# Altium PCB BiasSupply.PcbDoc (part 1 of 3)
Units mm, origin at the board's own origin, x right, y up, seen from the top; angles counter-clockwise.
Board outline 39 x 40.5 mm, 4 copper layers (Top Layer, Layer 2, Layer3, Bottom Layer), stack 0.661 mm thick; 168 components, 80 nets, 408 pads, 115 vias.
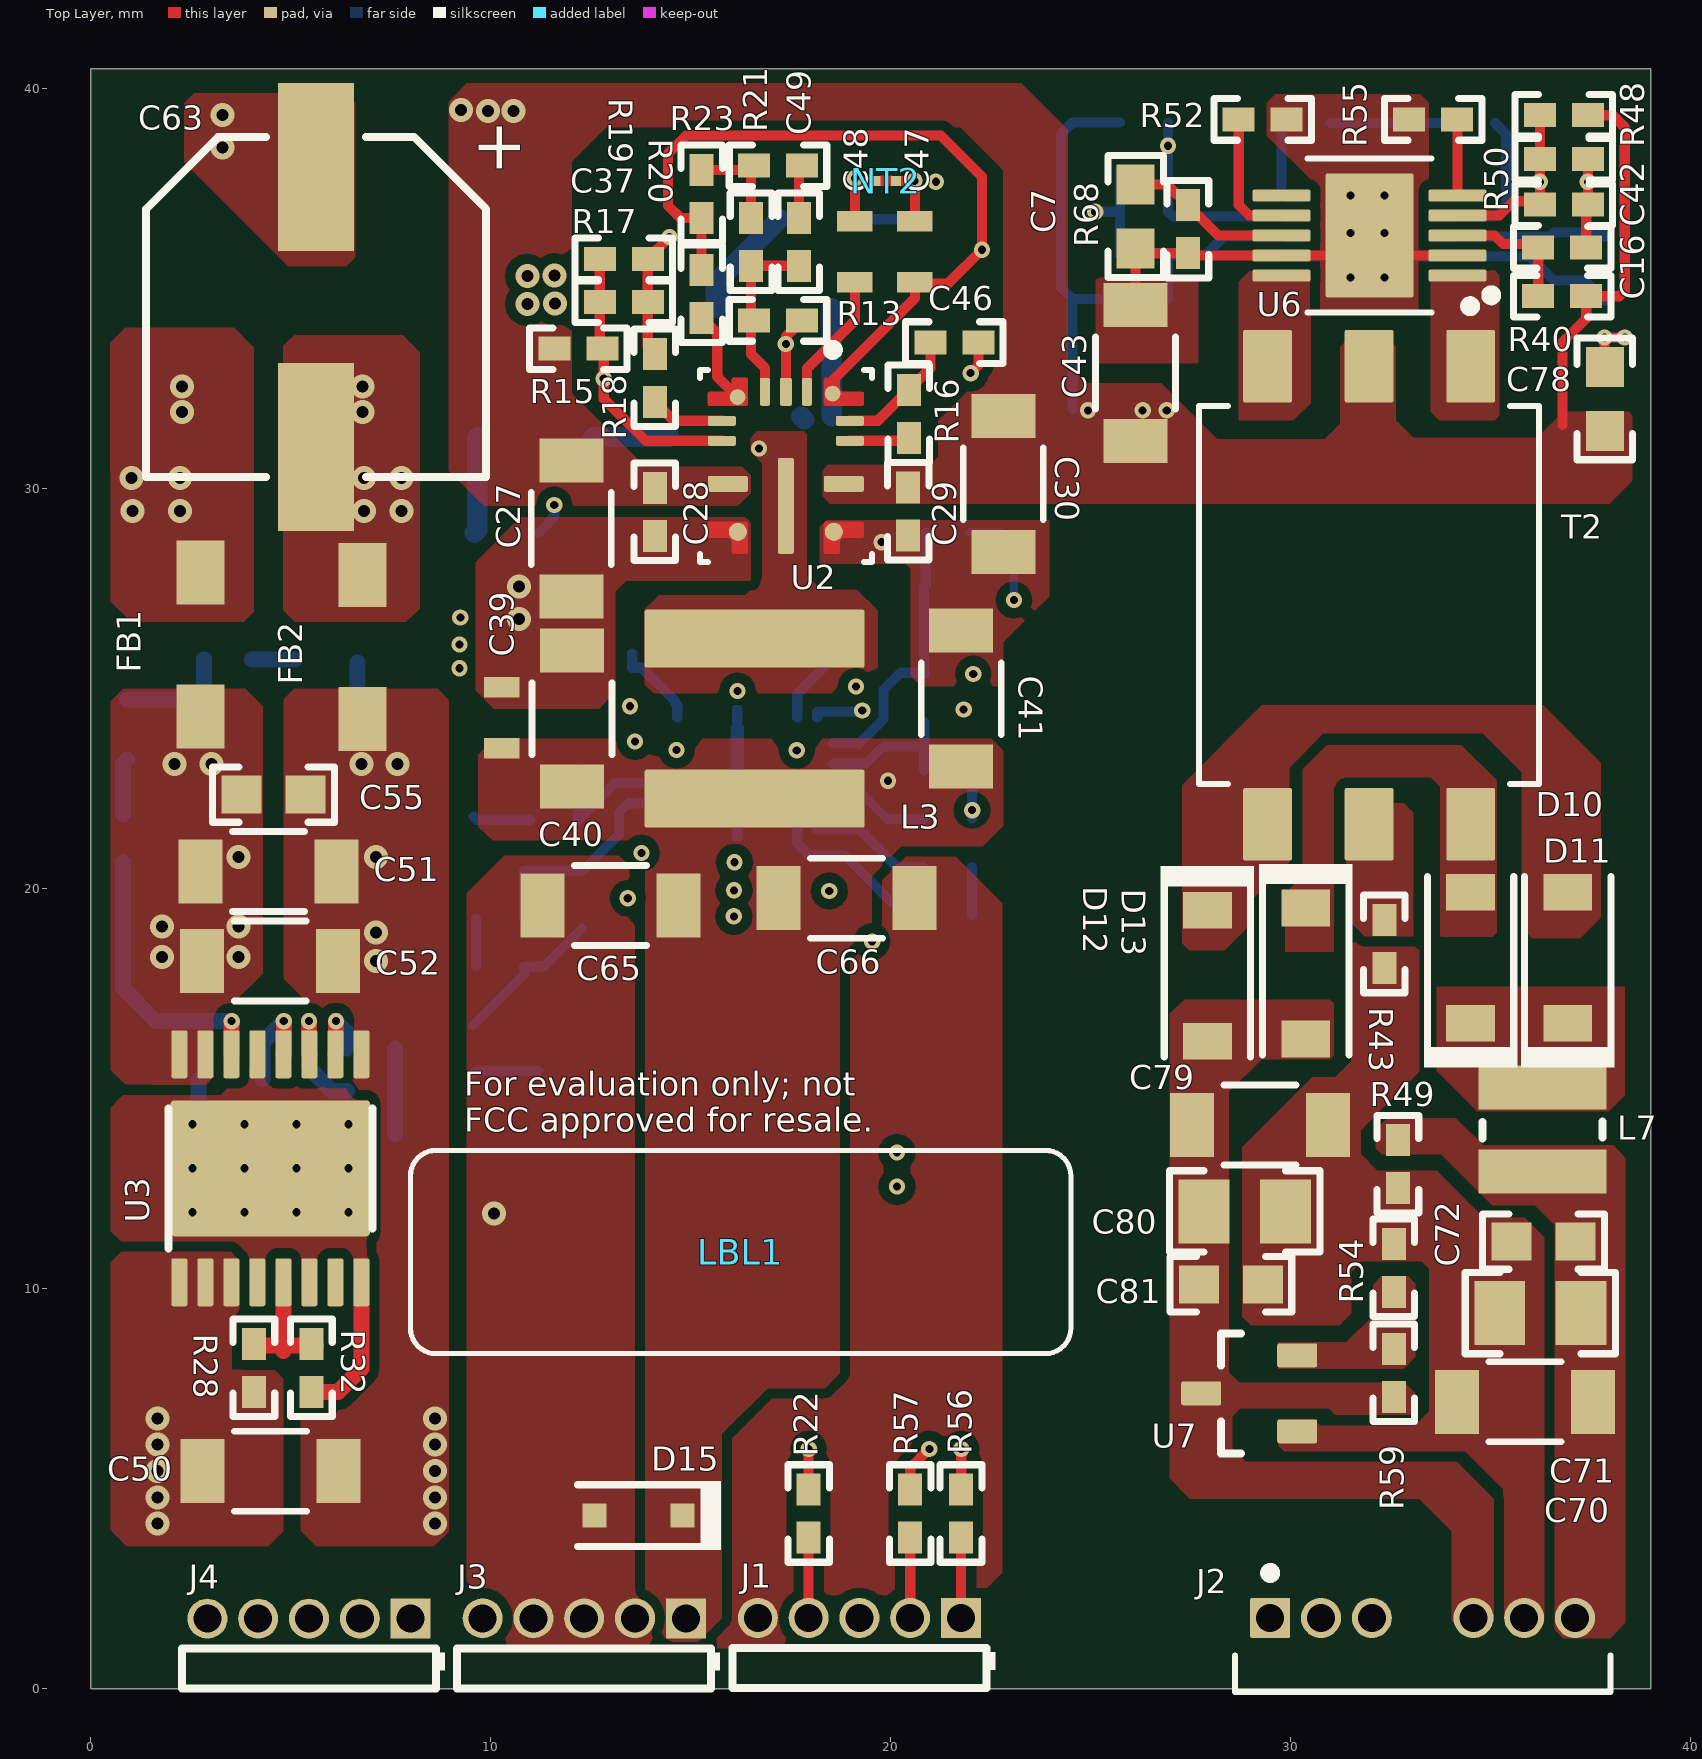
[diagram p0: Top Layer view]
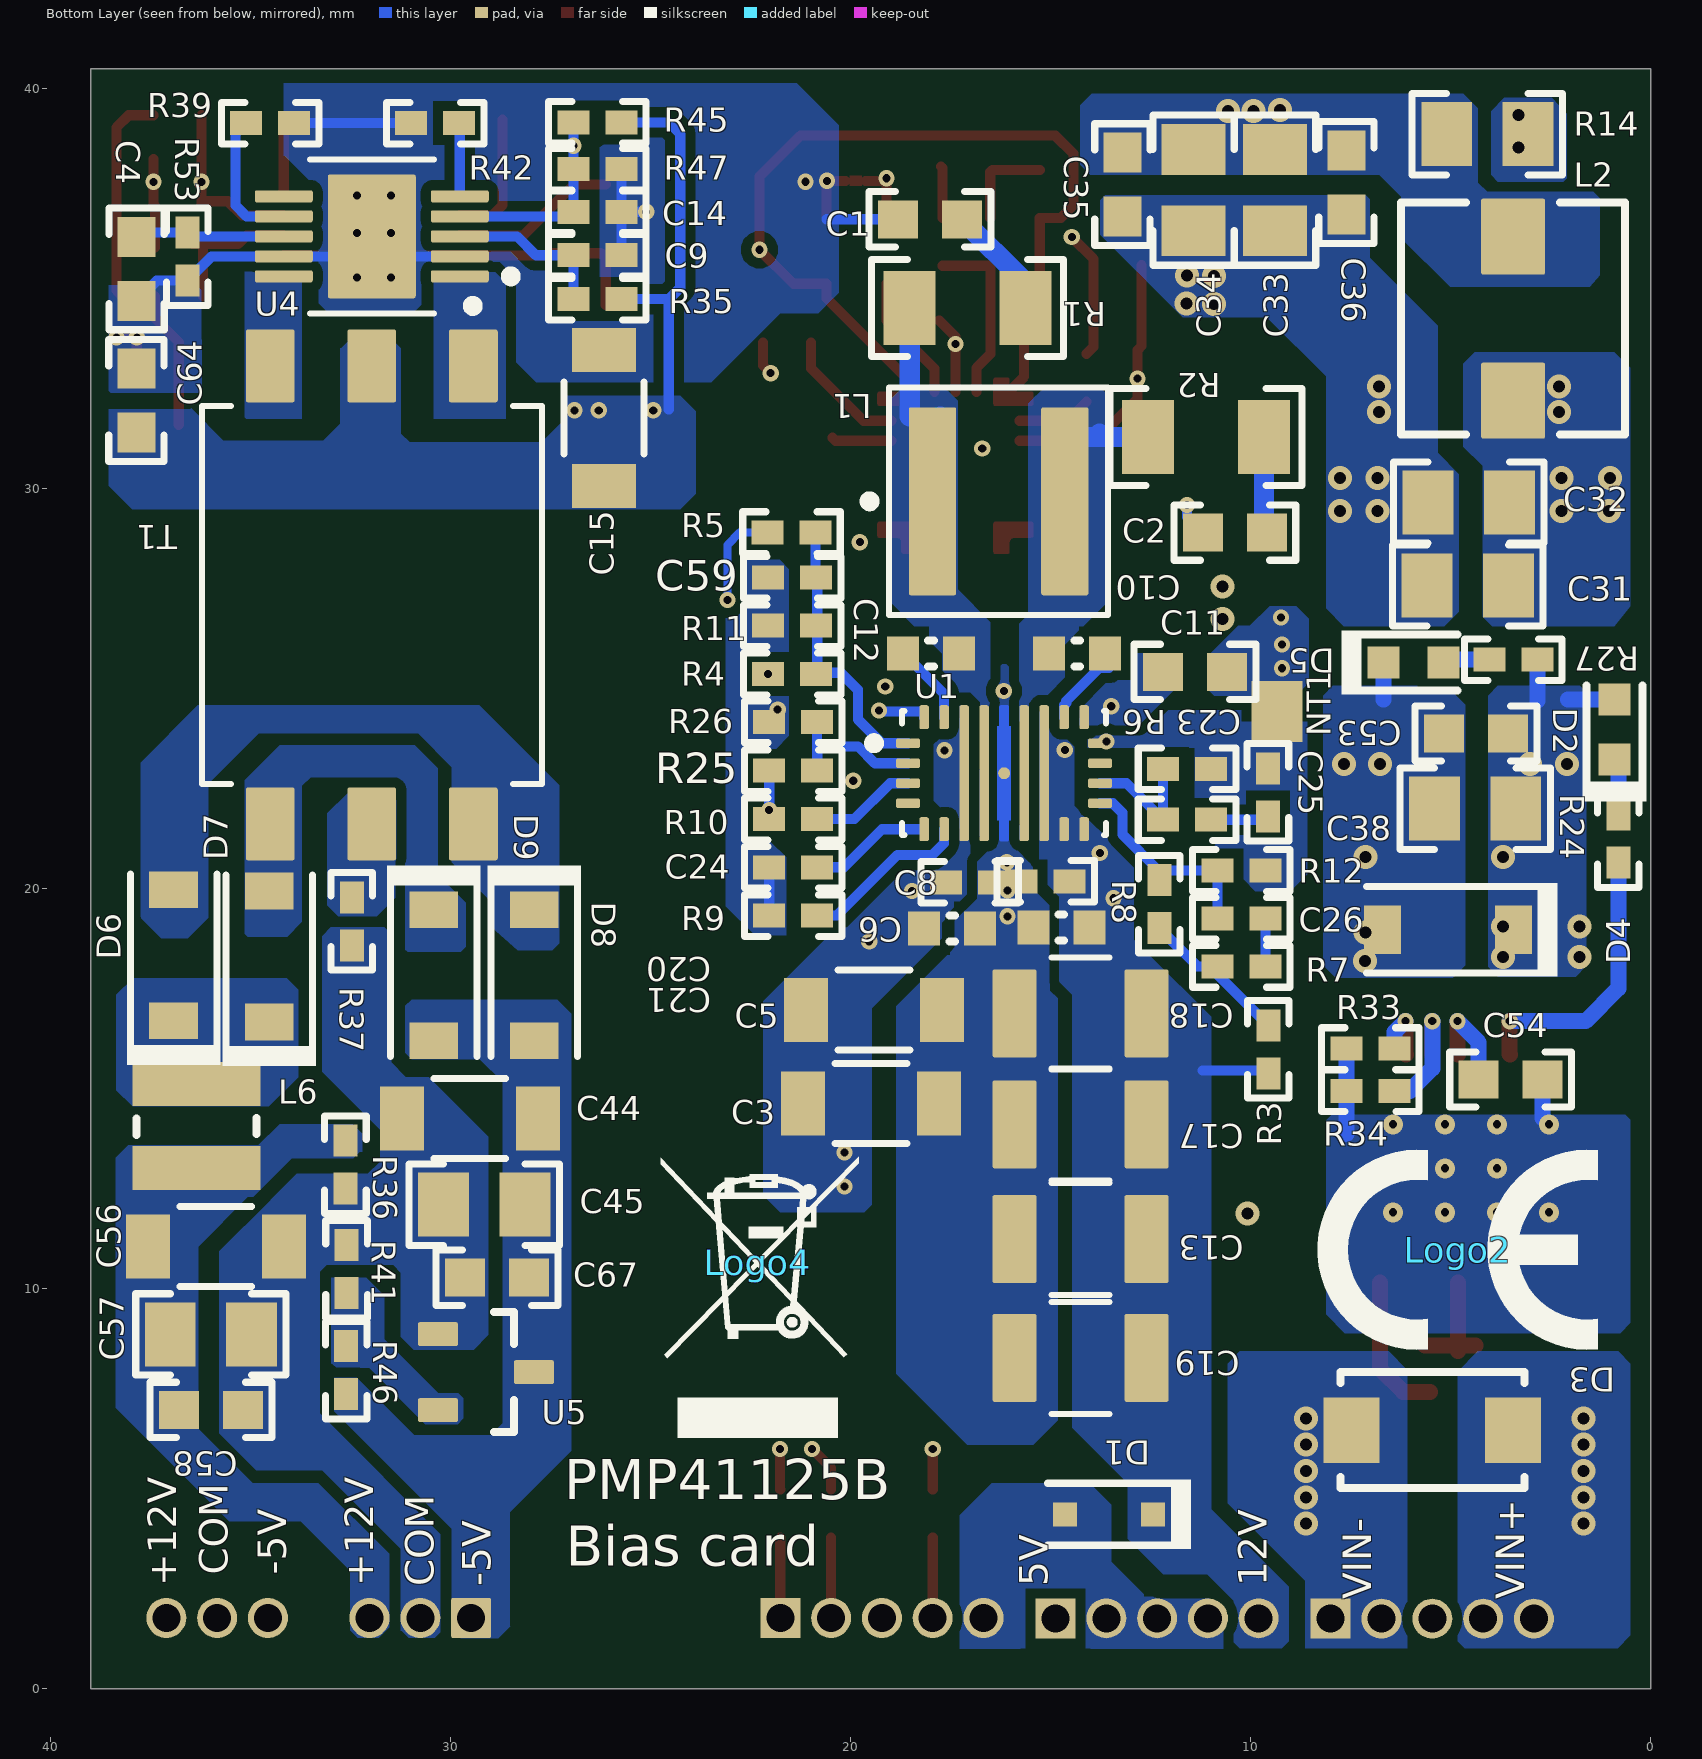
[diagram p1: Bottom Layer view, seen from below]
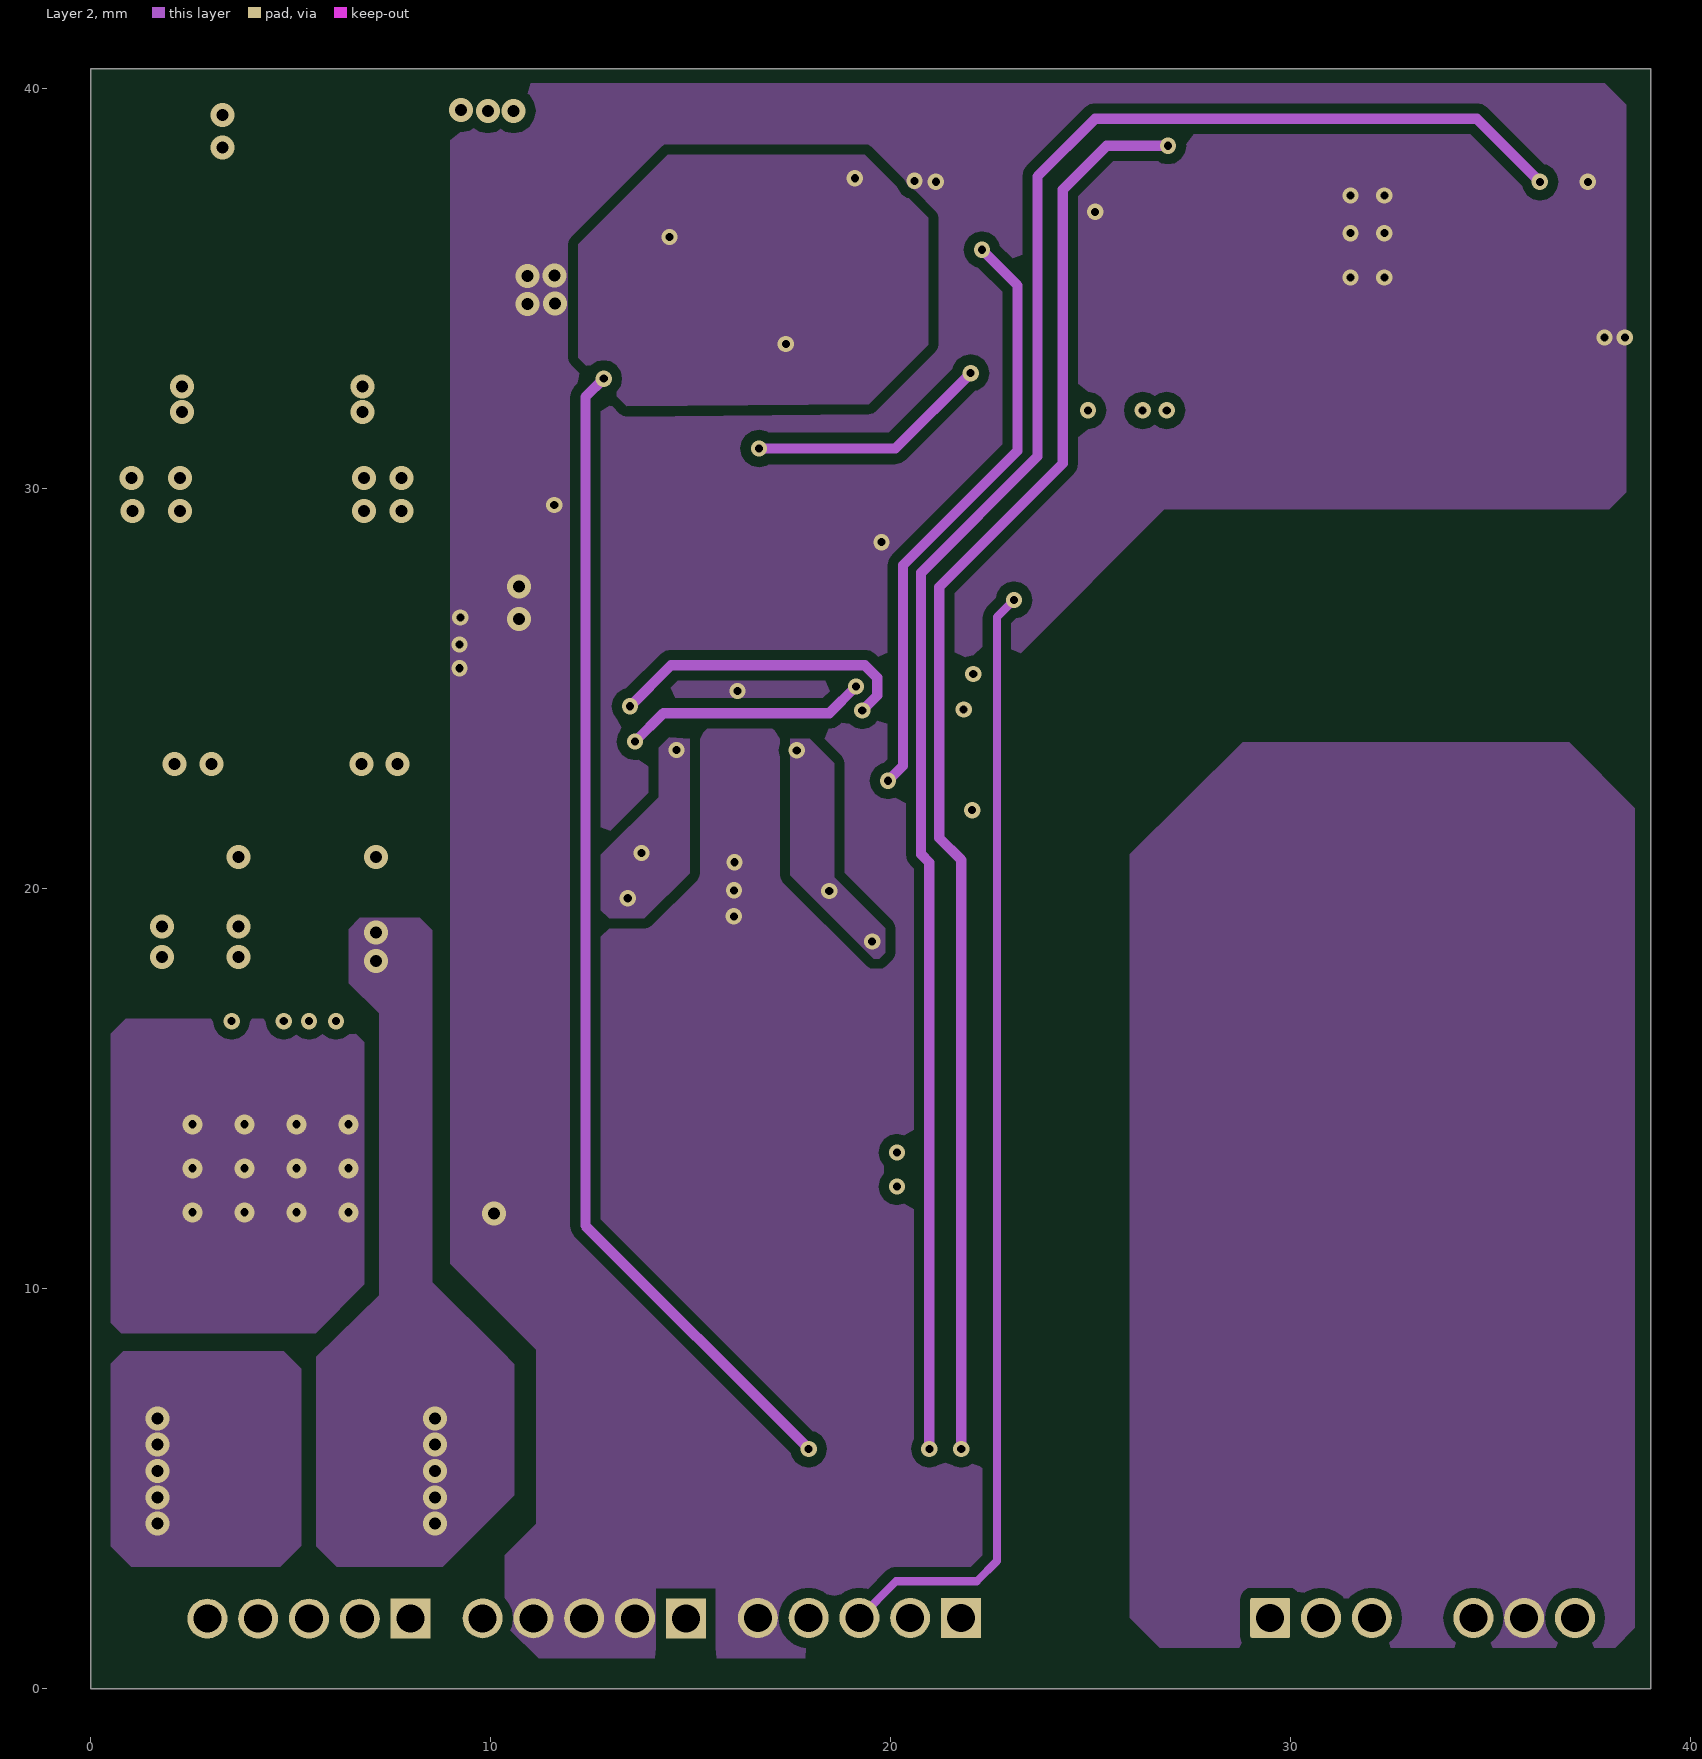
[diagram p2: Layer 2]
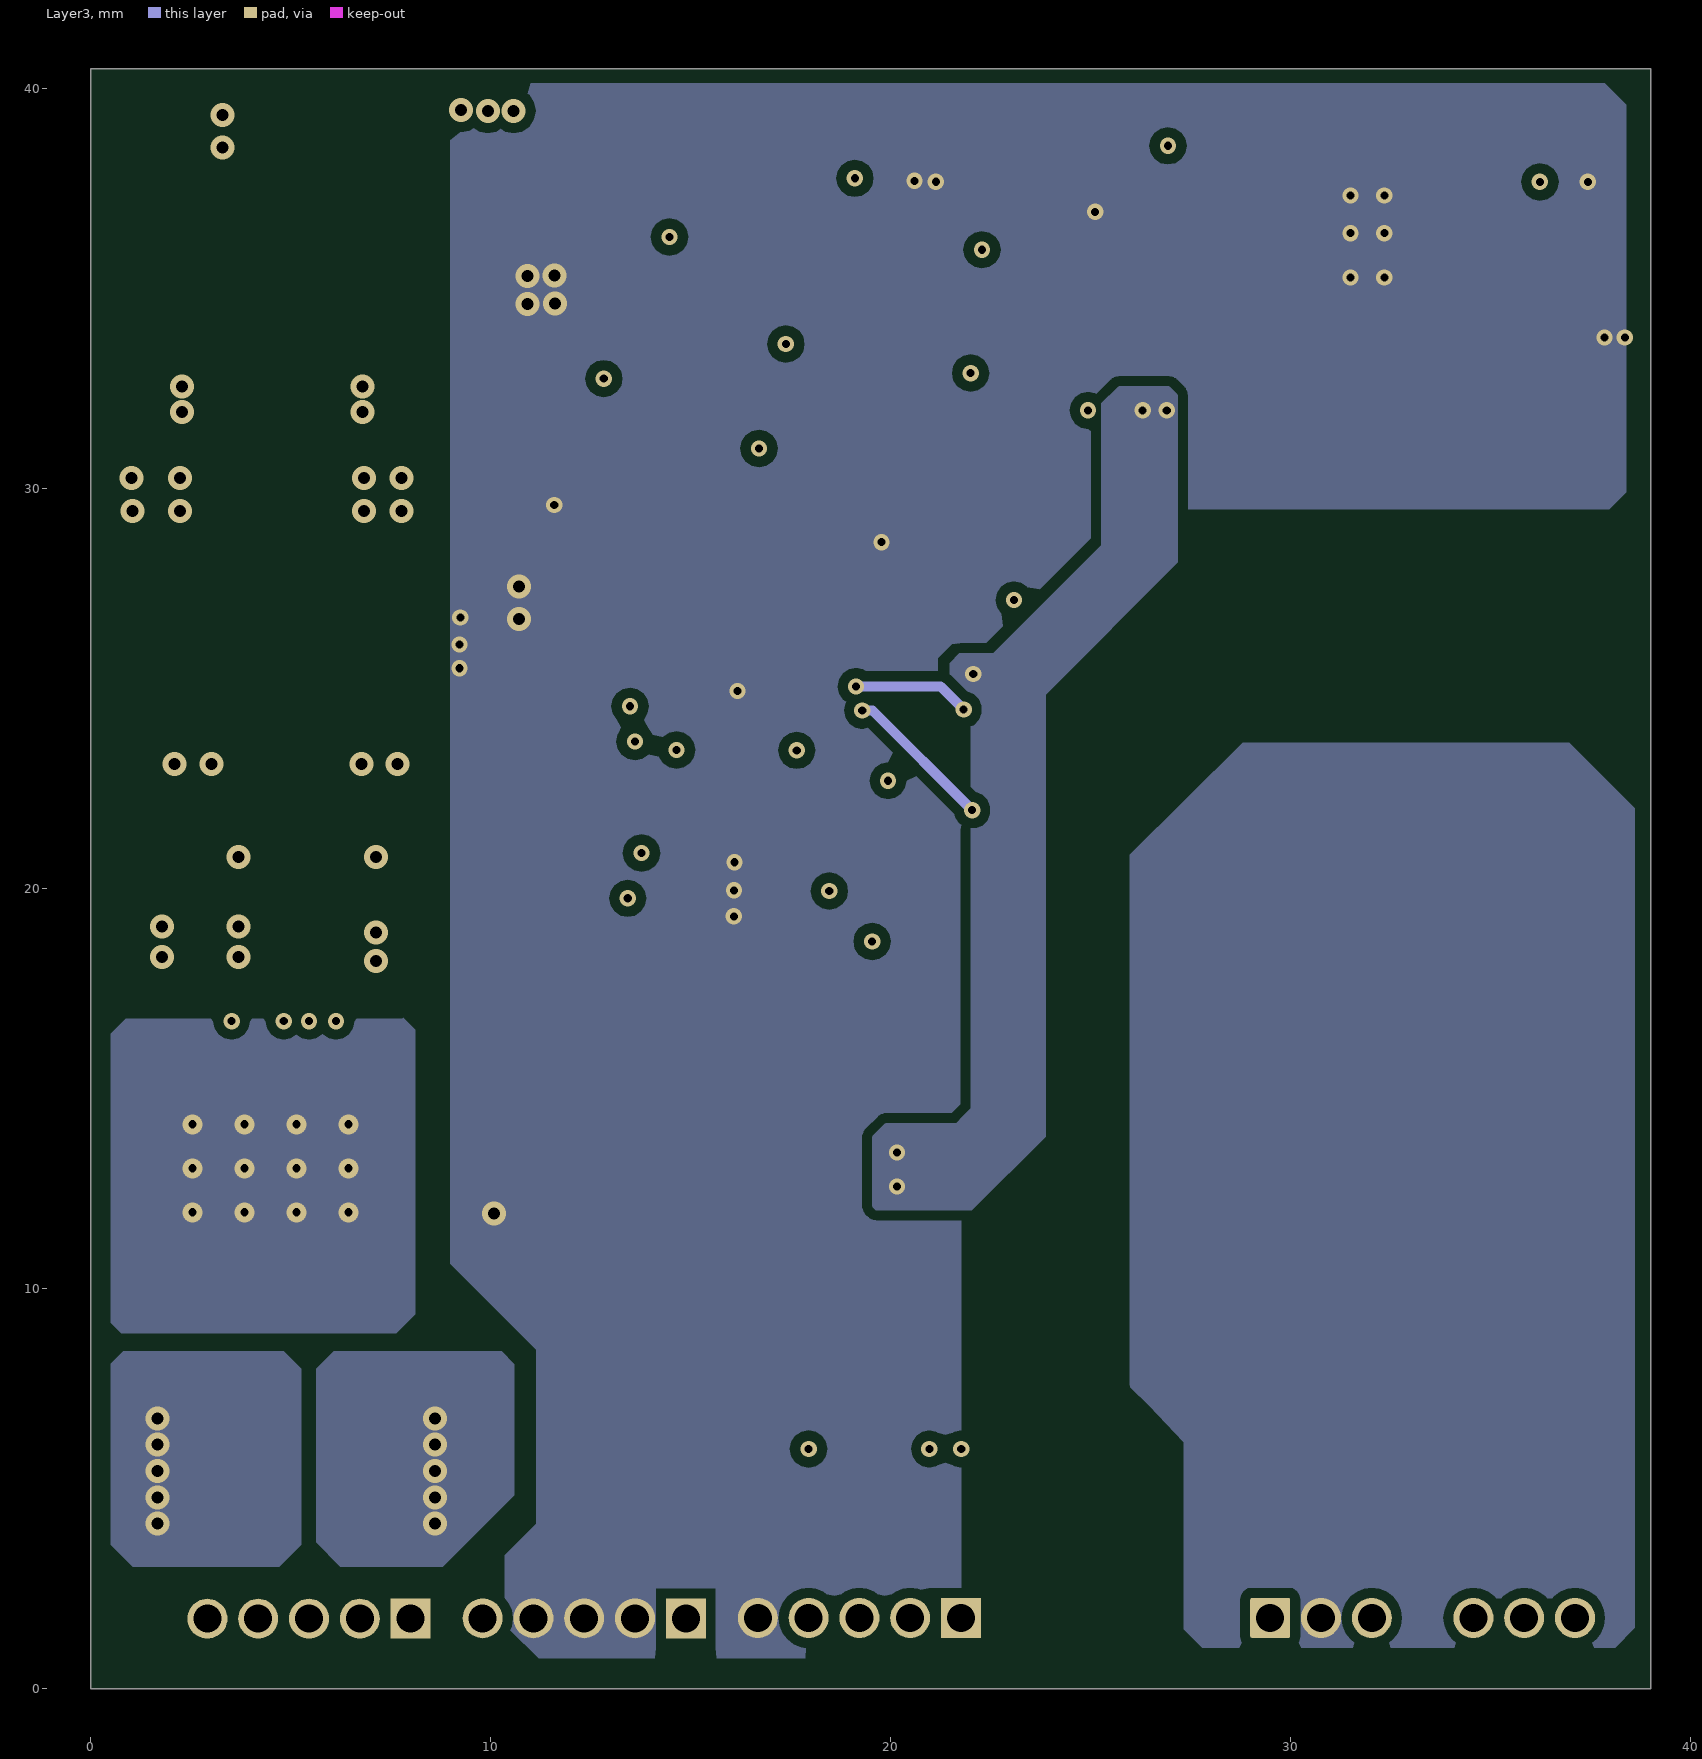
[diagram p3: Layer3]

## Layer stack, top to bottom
Top Solder: solder mask 0.0102, Solder Resist, Dk 3.5
Top Layer: signal copper 0.07
Dielectric1: prepreg 0.127, Dk 4.2
Layer 2: signal copper 0.07
Dielectric 3: prepreg 0.127, Dk 4.2
Layer3: signal copper 0.07
Dielectric 5: prepreg 0.127, Dk 4.2
Bottom Layer: signal copper 0.07
Bottom Solder: solder mask 0.0102, Solder Resist, Dk 3.5

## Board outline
0,0 0,40.5 39,40.5 39,0

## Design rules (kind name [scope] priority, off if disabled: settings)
AcuteAngle [All] p1: minimum=4.50000000000000E+0001 checktracksonly=FALSE
AssemblyTestPointUsage [All] p1: valid=2
Clearance Clearance_BoardEdge_MountingHoles [OnCopper and InComponentClass('Mounting Holes') vs IsKeepOut] p1: gap=1.016 ignorepadtopadclearanceinfootprint=FALSE except(0: Arc-Hole Track-Hole SMDPad-Hole THPad-Hole Via-Hole Fill-Hole Poly-Hole Region-Hole Text-Hole)
Clearance Clearance_BoardEdge_Poly [OnCopper and InPoly vs IsKeepOut] p2: gap=0.635 ignorepadtopadclearanceinfootprint=FALSE except(0: Arc-Hole Track-Hole SMDPad-Hole THPad-Hole Via-Hole Fill-Hole Poly-Hole Region-Hole Text-Hole)
Clearance Clearance_BoardEdge [OnCopper and Not InComponentClass('Logo') and not InComponentClass('FiducialMark') and not InRegion(1000,500,4000,800) and Not IsKeepout vs IsKeepOut] p3: gap=0.127 ignorepadtopadclearanceinfootprint=FALSE except(0: Arc-Hole Track-Hole SMDPad-Hole THPad-Hole Via-Hole Fill-Hole Poly-Hole Region-Hole Text-Hole)
Clearance Clearance_Poly [InPolygon] p4: gap=0.254 ignorepadtopadclearanceinfootprint=FALSE except(0: Arc-Hole Track-Hole SMDPad-Hole THPad-Hole Via-Hole Fill-Hole Poly-Hole Region-Hole Text-Hole)
Clearance [All] p5: gap=0.2 ignorepadtopadclearanceinfootprint=FALSE except(0: Arc-Hole Track-Hole SMDPad-Hole THPad-Hole Via-Hole Fill-Hole Poly-Hole Region-Hole Text-Hole)
ComponentClearance ComponentClearance_Logo [All] p1: gap=0.254 collisioncheckmode=3 verticalgap=0.254 showdistances=TRUE
ComponentClearance ComponentClearance_ScrewToNut [(HasFootprint('NY PMS 440 0025 PH')) vs (HasFootprint('Keystone_1902C'))] p2: gap=0.127 collisioncheckmode=3 verticalgap=0.254 showdistances=FALSE
ComponentClearance ComponentClearance_MountingHoles [InComponentClass('Mounting Holes')] p3: gap=0.254 collisioncheckmode=3 verticalgap=2540 showdistances=FALSE
ComponentClearance ComponentClearance_SmallPassives [HasFootprint('0201*') or HasFootprint('0402*') or HasFootprint('0508') or HasFootprint('0603*') or HasFootprint('0612') or HasFootprint('0805*') or HasFootprint('0815*') or HasFootprint('0830*') or HasFootprint('1206*') or HasFootprint('1210*') or HasFootprint('1808*') or HasFootprint('1812*') or HasFootprint('1825*') or HasFootprint('2010*') or HasFootprint('2220*') or HasFootprint('2225*') or HasFootprint('2512*') or HasFootprint('2728*') or HasFootprint('3518*') vs HasFootprint('0201*') or HasFootprint('0402*') or HasFootprint('0508') or HasFootprint('0603*') or HasFootprint('0612') or HasFootprint('0805*') or HasFootprint('0815*') or HasFootprint('0830*') or HasFootprint('1206*') or HasFootprint('1210*') or HasFootprint('1808*') or HasFootprint('1812*') or HasFootprint('1825*') or HasFootprint('2010*') or HasFootprint('2220*') or HasFootprint('2225*') or HasFootprint('2512*') or HasFootprint('2728*') or HasFootprint('3518*')] p4: gap=0.254 collisioncheckmode=3 verticalgap=0.254 showdistances=FALSE
ComponentClearance ComponentClearance_THtoSMT [IsThruComponent vs IsSMTComponent] p5: gap=0.254 collisioncheckmode=3 verticalgap=2540 showdistances=FALSE
ComponentClearance ComponentClearance_THtoTH [IsThruComponent vs IsThruComponent] p6: gap=0.254 collisioncheckmode=3 verticalgap=2540 showdistances=FALSE
ComponentClearance [All] p7: gap=0.254 collisioncheckmode=3 verticalgap=0.254 showdistances=FALSE
DiffPairsRouting [All] p1: maxlimit=2.54 minlimit=0.254 mostfreqgap=0.254 toplayer_minwidth=0.381 toplayer_maxwidth=0.381 toplayer_prefwidth=0.381 midlayer1_minwidth=0.381 midlayer1_maxwidth=0.381 midlayer1_prefwidth=0.381 midlayer4_minwidth=0.381 midlayer4_maxwidth=0.381 midlayer4_prefwidth=0.381 bottomlayer_minwidth=0.381 bottomlayer_maxwidth=0.381 bottomlayer_prefwidth=0.381 maxuncoupledlength=25.4
FabricationTestPointUsage TestPointUsage [All] p1: valid=2 allowmultiple=FALSE
FabricationTestpoint Testpoint [All] p1: side=3 testpointundercomponent=TRUE minsize=1.016 maxsize=2.54 preferedsize=1.524 minholesize=0 maxholesize=1.016 preferedholesize=0.813 testpointgrid=0.025 allowsidetop=TRUE allowsidebottom=TRUE usegrid=TRUE gridtolerance=0
FanoutControl Fanout_LCC [IsLCC] p1: bgadir=Out bgaviamode=Centered fanoutstyle=Auto fanoutdirection=Alternating viagrid=0.025 // Fanout_LCC (Default Rule)
FanoutControl Fanout_BGA [IsBGA] p2: bgadir=Out bgaviamode=Centered fanoutstyle=Auto fanoutdirection=Alternating viagrid=0.025 // Fanout_BGA (Default Rule)
FanoutControl Fanout_Default [All] p4: bgadir=Out bgaviamode=Centered fanoutstyle=Auto fanoutdirection=Alternating viagrid=0.025 // Fanout_Default (Default Rule)
FanoutControl Fanout_Small [(CompPinCount < 5)] p5: bgadir=Out bgaviamode=Centered fanoutstyle=Auto fanoutdirection=OutThenIn viagrid=0.025 // Fanout_Small (Default Rule)
HoleSize [All] p1: absolutevalues=TRUE maxlimit=6.375 minlimit=0.152 maxpercent=80.000 minpercent=20.000
MinimumAnnularRing [All] p1: minimumring=0.076
MinimumSolderMaskSliver MinimumSolderMaskSliver_Logo [InComponentClass('Logo') vs InComponentClass('Logo')] p1: minsoldermaskwidth=0.018
MinimumSolderMaskSliver [All] p2: minsoldermaskwidth=0
PlaneConnect [All] p1: planeconnectstyle=Direct reliefexpansion=0.254 reliefentries=4 reliefconductorwidth=0.254 reliefairgap=0.254
PolygonConnect [All] p1: connectstyle=Direct reliefconductorwidth=0.254 reliefentries=4 polygonreliefangle="90 Angle" airgapwidth=0.254
RoutingCorners [All] p1: cornerstyle=45-Degree minsetback=0.254 maxsetback=2.54
RoutingVias [All] p1: holewidth=0.406 width=0.864 viastyle="Through Hole" minholewidth=0.203 minwidth=0.406 maxholewidth=1.016 maxwidth=1.651
SMDToCorner [All] p1: distance=0
SilkToBoardRegionClearance [Not ((IsComment or IsDesignator) And (Hide <> 'False')) and not InRegion(1000,500,4000,800)] p1:
SilkToSilkClearance [All] p1: silktosilkclearance=0
SilkToSolderMaskClearance SilkscreenOverComponentPads [IsPad] p1: minsilkscreentomaskgap=0 clearancetoexposedcopper=TRUE
SolderMaskExpansion [All] p1: expansion=0.076 istentingtop=FALSE
Width [All] p1: maxlimit=2.54 minlimit=0.152 preferedwidth=0.254 checkconnectedcopper=TRUE
14 further rules are at their usual default settings.

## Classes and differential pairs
component class Label: LBL1
component class Header: J1 J3 J4
component class BiasSupply-SN6507-Q1: C4 C7 C9 C14 C15 C16 C42 C43 C44 C45 C56 C57 C58 C64 C67 C70 C71 C72 C78 C79 C80 C81 D6 D7 D8 D9 D10 D11 D12 D13 L6 L7 R35 R36 R37 R39 R40 R41 R42 R43 R45 R46 R47 R48 R49 R50 R52 R53 R54 R55 R56 R57 R59 R68 T1 T2 U4 U5 U6 U7
component class BiasSupply-LM74202-Q1: C50 C51 C52 C53 C54 D2 D3 D4 D5 J1 J2 J3 J4 R24 R27 R28 R32 R33 R34 U3
component class BiasSupply-LM61440-Q1: C27 C28 C29 C30 C31 C32 C33 C34 C35 C36 C37 C38 C39 C40 C41 C46 C47 C48 C49 C55 C63 C65 C66 D15 FB1 FB2 L2 L3 NT2 R13 R14 R15 R16 R17 R18 R19 R20 R21 R22 R23 U2
component class BiasSupply-TPS552872-Q1: C1 C2 C3 C5 C6 C8 C10 C11 C12 C13 C17 C18 C19 C20 C21 C23 C24 C25 C26 C59 D1 L1 NT1 R1 R2 R3 R4 R5 R6 R7 R8 R9 R10 R11 R12 R25 R26 U1
component class Logo: Logo1
component class BiasSupply_Hardware: LBL1 Logo1 Logo2 Logo3 Logo4 ZZ1 ZZ2 ZZ3 ZZ4
component class AssemblyNote: ZZ1 ZZ2 ZZ3 ZZ4

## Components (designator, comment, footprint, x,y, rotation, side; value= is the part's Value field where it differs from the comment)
C1 "C0603C102J5RACAUTO" 0603 18.018,36.735 r0 bottom value=1000pF
C2 "C0603C102J5RACAUTO" 0603 10.396,28.902 r0 bottom value=1000pF
C3 "CGA5L1X7R1H106K160AC" 1206_190 19.493,14.626 r180 bottom value=10uF
C4 "GRM188R71A225KE15J" 0603 37.854,35.497 r270 bottom value=2.2uF
C5 "CGA5L1X7R1H106K160AC" 1206_190 19.418,16.966 r180 bottom value=10uF
C6 "CGA3E1X7R1E105K080AC" 0603L 17.464,19.01 r0 bottom value=1uF
C7 "GRM188R71A225KE15J" 0603 26.124,36.801 r270 top value=2.2uF
C8 "GCM155R71H104KE02D" 0402 17.022,20.159 r180 bottom value=0.1uF
C9 "GCM155R71H104KE02D" 0402 26.332,35.837 r0 bottom value=0.1uF
C10 "CGA3E2X7R1H104K080AA" 0603L 17.991,25.885 r0 bottom value=0.1uF
C11 "GRT188R61C475KE13D" 0603 11.393,25.417 r180 bottom value=4.7uF
C12 "CGA3E2X7R1H104K080AA" 0603L 14.338,25.885 r180 bottom value=0.1uF
C13 "CGA6P3X7R1E226M250AB" FP-CGA6P3X7R1E226M250AB_1210-MFG 14.252,11.241 r0 bottom value=22µF
C14 "GCM155R71H104KE02D" 0402 26.332,36.921 r180 bottom value=0.1uF
C15 "CGA5L1X7R1H106K160AC" 1206_190 26.17,31.769 r90 bottom value=10uF
C16 "GCM155R71H104KE02D" 0402 36.788,36.031 r180 top value=0.1uF
C17 "CGA6P3X7R1E226M250AB" FP-CGA6P3X7R1E226M250AB_1210-MFG 14.252,14.106 r0 bottom value=22µF
C18 "CGA6P3X7R1E226M250AB" FP-CGA6P3X7R1E226M250AB_1210-MFG 14.252,16.881 r0 bottom value=22µF
C19 "CGA6P3X7R1E226M250AB" FP-CGA6P3X7R1E226M250AB_1210-MFG 14.252,8.27 r0 bottom value=22µF
C20 "GCM155R71H104KE02D" 0402 15.125,20.183 r0 bottom value=0.1uF
C21 "CGA3E1X7R1E105K080AC" 0603L 14.734,19.032 r180 bottom value=1uF
C23 "Capacitor" 0402 11.59,22.997 r180 bottom value=100pF
C24 "CGA2B3X7R1H103K050BB" 0402 21.437,20.535 r0 bottom value=0.01uF
C25 "CGA2B3X7R1H103K050BB" 0402 9.57,22.407 r90 bottom value=0.01uF
C26 "Capacitor" 0402 10.232,19.255 r0 bottom value=100pF
C27 "CGA5L1X7R1H106K160AC" 1206_190 12.017,29.006 r270 top value=10uF
C28 "CGA2B3X7R1H103K050BB" 0402 14.104,29.421 r270 top value=0.01uF
C29 "CGA2B3X7R1H103K050BB" 0402 20.437,29.433 r270 top value=0.01uF
C30 "CGA5L1X7R1H106K160AC" 1206_190 22.816,30.121 r270 top value=10uF
C31 "CF6" 0805_HV 4.572,27.578 r0 bottom value=2.2uF
C32 "CF5" 0805_HV 4.547,29.655 r0 bottom value=2.2uF
C33 "CF4" 0805_HV 9.388,37.466 r270 bottom value=2.2uF
C34 "CF3" 0805_HV 11.43,37.466 r270 bottom value=2.2uF
C35 "CF2" 0603 13.208,37.599 r270 bottom value=0.47uF
C36 "CF1" 0603 7.606,37.651 r270 bottom value=0.47uF
C37 "GCM155R71H104KE02D" 0402 13.328,35.745 r0 top value=0.1uF
C38 "CF6" 0805_HV 4.387,22 r0 bottom value=2.2uF
C39 "CGA3E1X7R1E105K080AC" 0603S 10.273,24.276 r90 top value=1uF
C40 "GCM31CR71A226KE02L" 1206_180 12.03,24.25 r270 top value=22uF
C41 "GCM31CR71A226KE02L" 1206_180 21.764,24.75 r270 top value=22uF
C42 "GCM155R71H104KE02D" 0402 36.83,37.101 r0 top value=0.1uF
C43 "CGA5L1X7R1H106K160AC" 1206_190 26.124,32.888 r90 top value=10uF
C44 "CGA5L1X7R1H106K160AC" 1206_190 29.523,14.257 r180 bottom value=10uF
C45 "GCM21BR71H105KA03K" 0805_HV 29.16,12.099 r180 bottom value=1uF
C46 "GCM155R71H104KE02D" 0402 21.593,33.652 r0 top value=0.1uF
C47 "CGA3E1X7R1E105K080AC" 0603S 20.604,35.921 r90 top value=1uF
C48 "CGA3E1X7R1E105K080AC" 0603S 19.104,35.921 r90 top value=1uF
C49 "CGA2B2NP01H220J050BA" 0402 17.704,36.171 r270 top value=22pF
C50 "CGA5L1X7R1H106K160AC" 1206_190 4.492,5.436 r0 top value=10uF
C51 "CGA5L1X7R1H106K160AC" 1206_190 4.448,20.432 r0 top value=10uF
C52 "CGA5L1X7R1H106K160AC" 1206_190 4.487,18.189 r0 top value=10uF
C53 "GCJ188R72A104KA01D" 0603 4.364,23.88 r0 bottom value=0.1uF
C54 "C0603C123K5RACTU" 0603 3.5,15.228 r180 bottom value=0.012uF
C55 "CF2" 0603 4.572,22.352 r0 top value=0.47uF
C56 "CGA5L1X7R1H106K160AC" 1206_190 35.872,11.057 r180 bottom value=10uF
C57 "GCM21BR71H105KA03K" 0805_HV 35.993,8.856 r180 bottom value=1uF
C58 "GCJ188R72A104KA01D" 0603 35.993,6.967 r180 bottom value=0.1uF
C59 "GCM155R71H102KA37D" 0402 21.464,27.781 r0 bottom value=1000pF
C63 "865080649013" WCAP-ASLI_D8H6.5 5.637,34.544 r90 top
C64 "GCJ188R72A104KA01D" 0603 37.854,32.203 r90 bottom value=0.1uF
C65 "GCM31CR71A226KE02L" 1206_180 12.996,19.581 r0 top value=22uF
C66 "GCM31CR71A226KE02L" 1206_180 18.896,19.761 r180 top value=22uF
C67 "GCJ188R72A104KA01D" 0603 28.844,10.275 r180 bottom value=0.1uF
C70 "CGA5L1X7R1H106K160AC" 1206_190 35.855,7.173 r180 top value=10uF
C71 "GCM21BR71H105KA03K" 0805_HV 36.243,9.389 r180 top value=1uF
C72 "GCJ188R72A104KA01D" 0603 36.324,11.179 r180 top value=0.1uF
C78 "GCJ188R72A104KA01D" 0603 37.854,32.246 r90 top value=0.1uF
C79 "CGA5L1X7R1H106K160AC" 1206_190 29.23,14.09 r180 top value=10uF
C80 "GCM21BR71H105KA03K" 0805_HV 28.851,11.933 r180 top value=1uF
C81 "GCJ188R72A104KA01D" 0603 28.503,10.109 r180 top value=0.1uF
D1 "SZMM3Z13VST1G" SOD-323 13.547,4.36 r0 bottom value=13V
D2 "CMP-0002842-2" LED_LTST-C190_Red 0.904,23.976 r270 bottom value=Red
D3 "SZ1SMA24CAT3G" SMA_Bi 5.459,6.461 r180 bottom value=24V
D4 "PMEG6010CEGWJ" SOD-123 5.068,18.975 r0 bottom value=60V
D5 "LTST-C190GKT" LED_LTST-C190 5.926,25.654 r0 bottom value=Green
D6 "PMEG6010CEGWJ" SOD-123 36.926,18.332 r90 bottom value=60V
D7 "PMEG6010CEGWJ" SOD-123 34.536,18.305 r90 bottom value=60V
D8 "PMEG6010CEGWJ" SOD-123 27.913,17.839 r270 bottom value=60V
D9 "PMEG6010CEGWJ" SOD-123 30.423,17.839 r270 bottom value=60V
D10 "PMEG6010CEGWJ" SOD-123 34.498,18.276 r90 top value=60V
D11 "PMEG6010CEGWJ" SOD-123 36.926,18.276 r90 top value=60V
D12 "PMEG6010CEGWJ" SOD-123 30.375,17.879 r270 top value=60V
D13 "PMEG6010CEGWJ" SOD-123 27.919,17.824 r270 top value=60V
D15 "SZMM3Z5V6ST1G" SOD-323 13.696,4.325 r180 top value=5.6V
FB1 "782763601" WE-CBA_1206_L3.2W1.6H1.1_HC 2.748,26.103 r90 top
FB2 "782763601" WE-CBA_1206_L3.2W1.6H1.1_HC 6.8,26.041 r90 top
J1 "GRPB051VWCN-RC" Sullins_xxxB051VWCN 19.219,1.768 r180 top locked
J2 "GRPB071VWCN-RC" FP-GRPB071VWCN-RC_HDR7-MFG 33.299,0.518 r0 top
J3 "GRPB051VWCN-RC" Sullins_xxxB051VWCN 12.339,1.76 r180 top locked
J4 "GRPB051VWCN-RC" Sullins_xxxB051VWCN 5.459,1.75 r180 top locked
L1 "XGL5030-102MEC" FP-XGL5030-102MEC_SMT_IND_5MM28_5MM48-MFG 16.301,29.685 r180 bottom value=1uH
L2 "744316220" FP-744316220_SMD2-MFG 3.439,34.25 r180 bottom
L3 "74439346047" WE-XHMI_6060 16.599,24.25 r270 top value=4.7uH
L6 "SRN3015TA-470M" SRN3015TA 36.352,14.067 r270 bottom value=47uH
L7 "SRN3015TA-470M" SRN3015TA 36.291,13.975 r270 top value=47uH
LBL1 "THT-14-423-10" Label_650x200 16.25,10.917 r180 top
Logo1 "Texas Instruments" TI_Stacked_Overlay_Small 80.01,1.016 r90 top
Logo2 "CE Mark" CE_Mark_5mm 4.826,10.975 r180 bottom
Logo3 "FCC disclaimer" FCC_disclaimer 59.817,84.912 r0 top
Logo4 "WEEE logo" WEEE_Minimum 22.327,10.643 r180 bottom
NT1 "Net-Tie" Net-Tie_50milWide_30milLong 9.34,24.424 r90 bottom net-tie
NT2 "Net-Tie" Net-Tie_10mil 19.875,37.696 r180 top net-tie
R1 "Resistor" 1206 17.075,34.519 r180 bottom value=2.20
R2 "Resistor" 1206 11.117,31.294 r0 bottom value=2.20
R3 "Resistor" 0402 9.559,15.985 r270 bottom value=49.9
R4 "CRCW040249K9FKED" 0402 21.464,25.367 r0 bottom value=49.9k
R5 "CRCW04020000Z0ED" 0402 21.479,28.902 r180 bottom value=0
R6 "CRCW04028K06FKED" 0402 11.59,21.723 r0 bottom value=8.06k
R7 "CRCW040210K0FKED" 0402 10.232,18.056 r0 bottom value=10.0k
R8 "Resistor" 0402 12.285,19.614 r270 bottom value=102k
R9 "CRCW04029K31FKED" 0402 21.437,19.328 r180 bottom value=9.31k
R10 "CRCW040224K9FKED" 0402 21.437,21.742 r180 bottom value=24.9k
R11 "CRCW040218K2FKED" 0402 21.464,26.574 r180 bottom value=18.2k
R12 "Resistor" 0402 10.232,20.454 r0 bottom value=11.3k
R13 "CRCW040224K9FKED" 0402 17.184,34.206 r180 top value=24.9k
R14 "ERJ-6RQFR47V" 0805_HV 4.084,38.862 r0 bottom value=0.47
R15 "CRCW040233K2FKED" 0402 12.193,33.5 r180 top value=33.2k
R16 "CRCW04020000Z0ED" 0402 20.453,31.871 r270 top value=0
R17 "CRCW04029K76FKED" 0402 13.328,34.671 r180 top value=9.76k
R18 "CRCW040233K2FKED" 0402 14.104,32.771 r270 top value=33.2k
R19 "CRCW0402100KDHEDP" 0402 15.275,34.871 r270 top value=100k
R20 "CRCW040249R9FKED" 0402 15.275,37.371 r270 top value=49.9
R21 "CRCW0402100KDHEDP" 0402 16.509,36.171 r90 top value=100k
R22 "CRCW04020000Z0ED" 0402 17.949,4.379 r90 top value=0
R23 "CRCW04021K21FKED" 0402 17.184,38.073 r0 top value=1.21k
R24 "CRCW040224K9FKED" 0402 0.809,21.253 r270 bottom value=24.9k
R25 "CRCW04020000Z0ED" 0402 21.437,22.949 r0 bottom value=0
R26 "CRCW04020000Z0ED" 0402 21.439,24.168 r180 bottom value=0
R27 "CRCW040224K9FKED" 0402 3.432,25.725 r180 bottom value=24.9k
R28 "CRCW040288K7FKED" 0402 4.081,8.022 r270 top value=88.7k
R32 "CRCW04024K64FKED" 0402 5.519,8.022 r90 top value=4.64k
R33 "CRCW040224K9FKED" 0402 7.008,16.002 r180 bottom value=24.9k
R34 "CRCW04025K36FKED" 0402 7.006,14.945 r180 bottom value=5.36k
R35 "CRCW04020000Z0ED" 0402 26.332,34.74 r180 bottom value=0
R36 "DNP" 0402 32.63,13.102 r90 bottom value=9.76k
R37 "CRCW04020000Z0ED" 0402 32.473,19.185 r270 bottom value=0
R39 "CRCW04029K76FKED" 0402 34.513,39.138 r0 bottom value=9.76k
R40 "CRCW04020000Z0ED" 0402 36.788,34.812 r0 top value=0
R41 "DNP" 0402 32.602,10.488 r90 bottom value=1.21k
R42 "CRCW040226K7FKED" 0402 30.388,39.138 r180 bottom value=26.7k
R43 "CRCW04020000Z0ED" 0402 32.342,18.618 r270 top value=0
R45 "CRCW040249K9FKED" 0402 26.332,39.157 r180 bottom value=49.9k
R46 "DNP" 0402 32.613,7.963 r90 bottom value=1.21k
R47 "CRCW040218K2FKED" 0402 26.332,37.987 r0 bottom value=18.2k
R48 "CRCW040249K9FKED" 0402 36.83,39.337 r0 top value=49.9k
R49 "DNP" 0402 32.68,13.115 r90 top value=9.76k
R50 "CRCW040218K2FKED" 0402 36.83,38.24 r180 top value=18.2k
R52 "CRCW04029K76FKED" 0402 29.302,39.232 r180 top value=9.76k
R53 "CRCW040218K2FKED" 0402 36.583,35.8 r90 bottom value=18.2k
R54 "DNP" 0402 32.579,10.521 r90 top value=1.21k
R55 "CRCW040226K7FKED" 0402 33.562,39.232 r0 top value=26.7k
R56 "CRCW04020000Z0ED" 0402 21.759,4.379 r90 top value=0
R57 "CRCW04020000Z0ED" 0402 20.489,4.379 r90 top value=0
R59 "DNP" 0402 32.579,7.896 r90 top value=1.21k
R68 "CRCW040218K2FKED" 0402 27.432,36.486 r90 top value=18.2k
T1 "750319691" FP-750319696_SMT_TRANSFORMER_9MM45_8MM50-MFG 31.973,27.344 r270 bottom
T2 "750319691" FP-750319696_SMT_TRANSFORMER_9MM45_8MM50-MFG 31.961,27.336 r270 top
U1 "TPS552872RYQR" RYQ0021A-MFG 16.165,22.886 r180 bottom
U2 "LM61430AASQRJRRQ1" RJR0014A-MFG 17.379,30.571 r270 top
U3 "LM74202QPWPRQ1" PWP0016H_L 4.492,13.01 r90 top
U4 "SN6507DGQRQ1" DGQ0010D-MFG 31.973,36.308 r0 bottom
U5 "DNP" DBZ0003A_N 29.119,7.914 r180 bottom
U6 "SN6507DGQRQ1" DGQ0010D-MFG 31.973,36.33 r180 top
U7 "DNP" DBZ0003A_N 28.964,7.384 r180 top
ZZ1 "This Assembly Note is for PCB labels only" AssemblyNoteLabel 4.699,100.025 r0 top
ZZ2 "These assemblies are ESD sensitive, ESD precautions shall be observed." AssemblyNote 4.699,97.259 r0 top
ZZ3 "These assemblies must be clean and free from flux and all contaminants. Use of no clean flux is not acceptable." AssemblyNote 4.699,95.01 r0 top
ZZ4 "These assemblies must comply with workmanship standards IPC-A-610 Class 2, unless otherwise specified." AssemblyNote 4.699,92.761 r0 top

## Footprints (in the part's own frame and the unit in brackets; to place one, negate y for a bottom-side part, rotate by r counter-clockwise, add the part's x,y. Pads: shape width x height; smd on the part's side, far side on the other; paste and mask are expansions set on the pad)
0402 [mm] "0402 from SM-752 data"
  rect 0.8x0.6 smd: 1(-0.6,0) 2(0.6,0)
  silkscreen extent -1.22,-0.52 1.22,0.52, body extent -0.55,-0.3 0.55,0.3, height 0.6
0603 [mm] "0603 from SM-752 data"
  rect 1x0.95 smd: 1(-0.8,0) 2(0.8,0)
  silkscreen extent -1.52,-0.69 1.52,0.69, body extent -0.87,-0.47 0.87,0.47, height 1
0603L [mm] "0603 from SM-752 data"
  rect 0.8x0.85 smd: 1(-0.7,0) 2(0.7,0)
  silkscreen extent -0.07,-0.33 0.07,0.33, body extent -0.87,-0.47 0.87,0.47, height 1
0603S [mil]
  rect 20x35 smd: 1(-30,0) 2(30,0)
  body extent -34,-19 34,19, height 39
0805_HV [mil] "0805 with 30mil clearance between pads"
  rect 50x63 smd: 1(-40,0) 2(40,0)
  silkscreen extent -74,-40 74,40, body extent -43,-29 43,29, height 57
1206 [mm] "1206 from SM-752 data"
  rect 1.3x1.85 smd: 1(-1.45,0) 2(1.45,0)
  silkscreen extent -2.4,-1.21 2.4,1.21, body extent -1.7,-0.9 1.7,0.9, height 1.35
1206_180 [mm] "1206_180"
  rect 1.1x1.6 smd: 1(-1.7,0) 2(1.7,0)
  silkscreen extent -0.9,-1 0.9,1, body extent -1.75,-0.95 1.75,0.95, height 1.8
1206_190 [mm] "1206_190"
  rect 1.1x1.6 smd: 1(-1.7,0) 2(1.7,0)
  silkscreen extent -0.9,-1 0.9,1, body extent -1.75,-0.95 1.75,0.95, height 1.9
AssemblyNote [mm] "Assembly Note"
AssemblyNoteLabel [mm] "Assembly Note for PCB Labels"
CE_Mark_5mm [mm] "Minimum text height for CE Mark"
  silkscreen extent -3.5,-2.5 3.5,2.5
DBZ0003A_N [mm] "SOT23, 3-Leads, Body 2.9x1.3mm, Pitch 0.95mm, Lead Span 2.4mm, IPC Medium Density"
  rrect17% 1x0.6 smd: 1(-1.2,0.95) 2(-1.2,-0.95) 3(1.2,0)
  silkscreen extent 0.2,-1.5 0.7,1.5, body extent -1.26,-1.46 1.26,1.46, height 0.98
DGQ0010D-MFG [mm]
  rrect33% 1.45x0.3 smd paste+0 mask+0: 1(-2.2,1) 2(-2.2,0.5) 3(-2.2,0) 4(-2.2,-0.5) 5(-2.2,-1) 6(2.2,-1) 7(2.2,-0.5) 8(2.2,0) 9(2.2,0.5) 10(2.2,1)
  rrect5% 2.2x3.1 smd paste-1000 mask-1000: 11(0,0)
  silkscreen extent -3.6,-1.92 1.55,1.92, body extent -2.46,-1.5 2.46,1.5, height 1.1
FCC_disclaimer [mm]
FP-744316220_SMD2-MFG [mm]
  rrect6% 1.6x1.9 smd paste+0 mask+0: 1(0,-2.05) 2(0,2.05)
  silkscreen extent -2.8,-2.9 2.8,2.9, body extent -2.65,-2.8 2.65,2.8, height 4.3
FP-750319696_SMT_TRANSFORMER_9MM45_8MM50-MFG [mm]
  rrect8% 1.82x1.22 smd paste+0 mask+0: 1(-5.725,2.54) 2(-5.725,0) 3(-5.725,-2.54) 4(5.725,-2.54) 5(5.725,0) 6(5.725,2.54)
  silkscreen extent -7.35,-4.25 4.72,4.25, body extent -6.44,-4.25 6.44,4.25, height 5
FP-CGA6P3X7R1E226M250AB_1210-MFG [mm]
  rrect9% 1.1x2.2 smd paste+0 mask+0: 1(-1.65,0) 2(1.65,0)
  silkscreen extent -0.72,-1.4 0.72,1.4, body extent -1.6,-1.25 1.6,1.25, height 2.81
FP-GRPB071VWCN-RC_HDR7-MFG [mm]
  rrect9% 1x1 hole 0.7 paste-1000 mask+0: 1(-3.81,1.25)
  round 1 hole 0.7 paste-1000 mask+0: 2(-2.54,1.25) 3(-1.27,1.25) 5(1.27,1.25) 6(2.54,1.25) 7(3.81,1.25)
  silkscreen extent -4.69,-0.6 4.69,2.5, body extent -4.79,-3.9 4.79,1.91, height 0.25
FP-XGL5030-102MEC_SMT_IND_5MM28_5MM48-MFG [mm]
  rrect8% 1.18x4.7 smd paste+0 mask+0: 1(-1.655,0) 2(1.655,0)
  silkscreen extent -3.35,-2.84 2.74,2.84, body extent -2.64,-2.74 2.64,2.74, height 3.1
Label_650x200 [mil] "Thermal Transfer Label"
  round 1 on Mech13: 0(0,0)
  silkscreen extent -325,-100 325,100, body extent -325,-100 325,100, height 1
LED_LTST-C190 [mm] "Lite-On"
  rect 0.8x0.8 smd: 1(-0.75,0) 2(0.75,0)
  silkscreen extent -1.1,-0.8 1.8,0.8, body extent -0.85,-0.45 0.85,0.45, height 0.9
LED_LTST-C190_Red [mm] "Lite-On"
  rect 0.8x0.8 smd: 1(-0.75,0) 2(0.75,0)
  silkscreen extent -1.1,-0.8 1.8,0.8, body extent -0.85,-0.45 0.85,0.45, height 0.9
Net-Tie_10mil [mil] "10mil net tie, no solder mask opening, no solder paste"
  rect 10x10 smd paste-5 mask-5: 1(-10,0) 2(10,0)
  Top Layer region: -6,5 6,5 6,-5 -6,-5
Net-Tie_50milWide_30milLong [mil] "50mil net tie, no solder mask opening, no solder paste"
  rect 30x50 smd paste-20 mask-20: 1(-15,0) 2(15,0)
PWP0016H_L [mm] "TSOP, 16-Leads, Body 5x4.4mm, Pitch 0.65mm, Thermal Pad 2.48x3.37 mm, IPC High Density"
  rrect25% 1.2x0.4 smd: 1(-2.85,2.275) 2(-2.85,1.625) 3(-2.85,0.975) 4(-2.85,0.325) 5(-2.85,-0.325) 6(-2.85,-0.975) 7(-2.85,-1.625) 8(-2.85,-2.275) 9(2.85,-2.275) 10(2.85,-1.625) 11(2.85,-0.975) 12(2.85,-0.325) 13(2.85,0.325) 14(2.85,0.975) 15(2.85,1.625) 16(2.85,2.275)
  rrect6% 3.4x5 smd paste-2 mask-2: 17(0,0)
  rrect4% 2.66x2.46 on Top Solder: 17(0,0)
  rrect4% 2.66x2.46 on Top Paste: 17(0,0)
  silkscreen extent -2,-2.55 1.5,2.55, body extent -3.2,-2.5 3.2,2.5, height 1.13
RJR0014A-MFG [mm]
  round 0.394 smd paste-1000 mask+0: 1(-1.806,1.169) 5(-1.719,-1.206)
  rrect40% 0.7x0.25 smd paste+0 mask+0: 2(-1.85,0.525) 4(-1.85,-0.525)
  rrect33% 0.7x0.3 smd paste+0 mask+0: 3(-1.85,0)
  rrect40% 0.25x0.7 smd paste+0 mask+0: 6(-1.125,-1.6) 7(-0.625,-1.6) 13(-0.625,1.6) 14(-1.125,1.6)
  rrect25% 0.4x1 smd paste+0 mask+0: 8(0.45,-1.45) 12(0.45,1.45)
  round 0.45 smd paste-1000 mask+0: 9(1.65,-1.2) 11(1.65,1.2)
  rrect25% 2.4x0.4 smd paste-1000 mask+0: 10(1,0)
  Top Layer region: 1.45,-1.95 1.75,-1.95 1.769,-1.946 1.785,-1.935 1.796,-1.919 1.8,-1.9 1.8,-1.9 1.8,-1.47 1.816,-1.41 1.86,-1.366 1.92,-1.35 1.92,-1.35 2.15,-1.35 2.169,-1.346 2.185,-1.335 2.196,-1.319 2.2,-1.3 2.2,-1.3 2.2,-1 2.193,-0.975 2.175,-0.957 2.15,-0.95 2.15,-0.95 1.45,-0.95 1.431,-0.954 1.415,-0.965 1.404,-0.981 1.4,-1 1.4,-1 1.4,-1.9 1.404,-1.919 1.415,-1.935 1.431,-1.946 1.45,-1.95 1.45,-1.95
  Top Layer region: 1.45,1.95 1.75,1.95 1.769,1.946 1.785,1.935 1.796,1.919 1.8,1.9 1.8,1.9 1.8,1.47 1.816,1.41 1.86,1.366 1.92,1.35 1.92,1.35 2.15,1.35 2.169,1.346 2.185,1.335 2.196,1.319 2.2,1.3 2.2,1.3 2.2,1 2.193,0.975 2.175,0.957 2.15,0.95 2.15,0.95 1.45,0.95 1.431,0.954 1.415,0.965 1.404,0.981 1.4,1 1.4,1 1.4,1.9 1.404,1.919 1.415,1.935 1.431,1.946 1.45,1.95 1.45,1.95
  Top Layer region: -1.55,-1.95 -1.531,-1.946 -1.515,-1.935 -1.504,-1.919 -1.5,-1.9 -1.5,-1.9 -1.5,-1 -1.507,-0.975 -1.525,-0.957 -1.55,-0.95 -1.55,-0.95 -2.15,-0.95 -2.175,-0.957 -2.193,-0.975 -2.2,-1 -2.2,-1 -2.2,-1.3 -2.196,-1.319 -2.185,-1.335 -2.169,-1.346 -2.15,-1.35 -2.15,-1.35 -1.97,-1.35 -1.924,-1.359 -1.885,-1.385 -1.859,-1.424 -1.85,-1.47 -1.85,-1.47 -1.85,-1.9 -1.846,-1.919 -1.835,-1.935 -1.819,-1.946 -1.8,-1.95 -1.8,-1.95
  Top Layer region: -1.8,1.95 -1.55,1.95 -1.531,1.946 -1.515,1.935 -1.504,1.919 -1.5,1.9 -1.5,1.9 -1.5,1 -1.507,0.975 -1.525,0.957 -1.55,0.95 -1.55,0.95 -2.15,0.95 -2.175,0.957 -2.193,0.975 -2.2,1 -2.2,1 -2.2,1.3 -2.196,1.319 -2.185,1.335 -2.169,1.346 -2.15,1.35 -2.15,1.35 -1.97,1.35 -1.924,1.359 -1.885,1.385 -1.859,1.424 -1.85,1.47 -1.85,1.47 -1.85,1.9 -1.846,1.919 -1.835,1.935 -1.819,1.946 -1.8,1.95 -1.8,1.95
  silkscreen extent -3.02,-2.15 2.4,2.15, body extent -2.3,-2.05 2.3,2.05, height 0.25
RYQ0021A-MFG [mm]
  rrect42% 0.6x0.24 smd paste+0 mask+0: 1(-2.4,0.75) 2(-2.4,0.25) 3(-2.4,-0.25) 4(-2.4,-0.75) 14(2.4,-0.75) 15(2.4,-0.25) 16(2.4,0.25) 17(2.4,0.75)
  rrect42% 0.24x0.6 smd paste+0 mask+0: 5(-2,-1.4) 6(-1.5,-1.4) 12(1.5,-1.4) 13(2,-1.4) 18(2,1.4) 19(1.5,1.4) 20(-1.5,1.4) 21(-2,1.4)
  rrect42% 0.24x3.4 smd paste-1000 mask+0: 7(-1,0) 8(-0.5,0) 10(0.5,0) 11(1,0)
  round 0.297 smd paste-1000 mask+0: 9(0,0)
  Top Layer region: -0.165,-1.175 -0.165,1.175 -0.12,1.175 -0.12,1.65 -0.113,1.675 -0.095,1.693 -0.07,1.7 -0.07,1.7 0.07,1.7 0.095,1.693 0.113,1.675 0.12,1.65 0.12,1.65 0.12,1.175 0.165,1.175 0.165,-1.175 0.12,-1.175 0.12,-1.65 0.113,-1.675 0.095,-1.693 0.07,-1.7 0.07,-1.7 -0.07,-1.7 -0.095,-1.693 -0.113,-1.675 -0.12,-1.65 -0.12,-1.65 -0.12,-1.175
  silkscreen extent -3.38,-1.55 2.55,1.55, body extent -2.5,-1.5 2.5,1.5, height 1
SMA_Bi [mm] "SMD, 2-Leads, Body 4.275x2.575mm"
  rect 1.4x1.64 smd: 1(-2.015,0) 2(2.015,0)
  silkscreen extent -2.3,-1.45 2.3,1.45, body extent -2.52,-1.45 2.52,1.45, height 2.65
SOD-123 [mm] "On Semi recommended land pattern"
  rect 0.915x1.22 smd: 1(-1.637,0) 2(1.637,0)
  silkscreen extent -2.74,-1.17 2.03,1.17, body extent -1.93,-0.9 1.93,0.9, height 1.35
SOD-323 [mm] "NXP recommended land pattern"
  rect 0.6x0.6 smd paste-0.05: 1(-1.1,0) 2(1.1,0)
  silkscreen extent -2.06,-0.86 1.53,0.86, body extent -1.3,-0.67 1.3,0.68, height 1.1
SRN3015TA [mm] "SMD, 2-Leads, Body 3x3mm"
  rect 1.1x3.2 smd: 1(-1.05,0) 2(1.05,0)
  silkscreen extent -0.2,-1.5 0.22,1.5, body extent -1.5,-1.52 1.5,1.52, height 1.48
Sullins_xxxB051VWCN [mm] "Header, 1.27mm, 5x1, RA, TH"
  rect 1x1 hole 0.7: 1(-2.54,0)
  round 1 hole 0.7: 2(-1.27,0) 3(0,0) 4(1.27,0) 5(2.54,0)
  silkscreen extent -3.4,0.75 3.17,1.75, body extent -3.18,-0.2 3.17,4.75, height 2.34
TI_Stacked_Overlay_Small [mm]
  silkscreen extent -10.63,-2.49 10.63,2.49
WCAP-ASLI_D8H6.5 [mm] "Aluminium Electrolytic V-Chip SMT Capacitors, 8x6.5mm"
  rect 4.2x1.9 smd: 1(3.5,0) 2(-3.5,0)
  silkscreen extent -4.25,-4.25 4.25,4.25, body extent -4.5,-4.15 4.5,4.15, height 6.45
WE-CBA_1206_L3.2W1.6H1.1_HC [mm] "SMD EMI Suppression Ferrite Bead, 2-Leads, body 3.20x1.60mm"
  rect 1.6x1.2 smd: 1(-1.8,0) 2(1.8,0)
  body extent -1.6,-0.8 1.6,0.8, height 1.1
WE-XHMI_6060 [mm] "SMD, 2-Leads, Body 6.65x6.45mm"
  rrect7% 1.45x5.5 smd: 1(-2,0) 2(2,0)
  body extent -3.23,-3.32 3.22,3.33, height 5.78
WEEE_Minimum [mm] "WEEElie bin"
  silkscreen extent -2.42,-4.38 2.52,2.65

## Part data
C1 C2: library part CMP-0006844-4, "CAP, CERM, 1000 pF, 50 V, +/- 5%, X7R, AEC-Q200 Grade 1, 0603", Cap_Case=0603, Manufacturer=Kemet, Supplier Part Number 1=399-12989-1-ND, TempCo=X7R, Tolerance_%=5%, Value1=Unknown, Value2=50V, ValueDisplayed=1000pF
C3 C5 C15 C27 C30 C43 C44 C50 C51 C52 C56 C70 C79: library part CMP-0085950-1, "CAP, CERM, 10 µF, 50 V,+/- 10%, X7R, AEC-Q200 Grade 1, 1206", Cap_Case=1206, Manufacturer=TDK, TempCo=X7R, Tolerance_%=10%, Value2=50V, ValueDisplayed=10µF
C4 C7: library part CMP-0084284-1, "CAP, CERM, 2.2 µF, 10 V,+/- 10%, X7R, AEC-Q200 Grade 1, 0603", Cap_Case=0603, Manufacturer=MuRata, TempCo=X7R, Tolerance_%=10%, Value2=10V, ValueDisplayed=2.2µF
C6 C21 C39 C47 C48: library part CMP-0076705-2, "CAP, CERM, 1 µF, 25 V,+/- 10%, X7R, AEC-Q200 Grade 1, 0603", Cap_Case=1.6x0.8x0.8mm, Manufacturer=TDK, Supplier Part Number 1=445-6931-1-ND, TempCo=X7R, Tolerance_%=10%, Value2=25V, ValueDisplayed=1µF
C8 C9 C14 C16 C20 C37 C42 C46: library part CMP-0006356-2, "CAP, CERM, 0.1 uF, 50 V, +/- 10%, X7R, AEC-Q200 Grade 1, 0402", Cap_Case=0402, Manufacturer=MuRata, Supplier Part Number 1=490-10672-1-ND, TempCo=X7R, Tolerance_%=10%, Value1=Unknown, Value2=50V, ValueDisplayed=0.1uF
C10 C12: library part CMP-0007078-1, "CAP, CERM, 0.1 uF, 50 V, +/- 10%, X7R, AEC-Q200 Grade 1, 0603", Cap_Case=0603, Manufacturer=TDK, Supplier Part Number 1=445-5666-1-ND, TempCo=X7R, Tolerance_%=10%, Value1="0.0296 ohm", Value2=50V, ValueDisplayed=0.1uF
C11: library part CMP-0081052-1, "CAP, CERM, 4.7 µF, 16 V,+/- 10%, X5R, AEC-Q200 Grade 3, 0603", Cap_Case=0603, Manufacturer=MuRata, Supplier Part Number 1=490-12319-1-ND, TempCo=X5R, Tolerance_%=10%, Value2=16V, ValueDisplayed=4.7µF
C13 C17 C18 C19: library part CMP-0036912-1, "Cap Ceramic 22uF 25V X7R 20% Pad SMD 1210 +125°C Automotive T/R", Manufacturer=TDK, Operating Temperature Range="-55°C to +125°C", TempCo=15%, Temperature Characteristic=X7R, Tolerance_%=0.2%, ValueDisplayed=22uF
C23 C26: library part CMP-0006308-2, "CAP, CERM, 100 pF, 50 V, +/- 5%, C0G/NP0, AEC-Q200 Grade 1, 0402", Cap_Case=0402, Manufacturer=TDK, PartNumber=CGA2B2C0G1H101J050BA, Supplier Part Number 1=445-5596-1-ND, TempCo=C0G/NP0, Tolerance_%=5%, Value1=Unknown, Value2=50V, ValueDisplayed=100pF
C24 C28 C29: library part CMP-0006324-2, "CAP, CERM, 0.01 uF, 50 V, +/- 10%, X7R, AEC-Q200 Grade 1, 0402", Cap_Case=0402, Manufacturer=TDK, Supplier Part Number 1=445-6893-1-ND, TempCo=X7R, Tolerance_%=10%, Value1="0.333065 ohm", Value2=50V, ValueDisplayed=0.01uF
C25: library part CMP-0006324-2, "CAP, CERM, 0.01 uF, 50 V, +/- 10%, X7R, AEC-Q200 Grade 1, 0402", Cap_Case=0402, Manufacturer=TDK, Supplier Part Number 1=445-6893-1-ND, TempCo=X7R, Tolerance_%=10%, Value1="0.333065 ohm", Value2=50V, ValueDisplayed=10nF
C31 C32 C33 C34 C38: library part CMP-0007977-2, "CAP, CERM, 2.2 uF, 50 V, +/- 10%, X7R, AEC-Q200 Grade 1, 0805", Cap_Case=0805, Manufacturer=TDK, PartNumber=CGA4J3X7R1H225K125AB, Supplier Part Number 1=445-174216-1-ND, TempCo=X7R, Tolerance_%=10%, Value1="0.003288 ohm", Value2=50V, ValueDisplayed=2.2uF
C35 C36 C55: library part CMP-0007097-4, "CAP, CERM, 0.47 uF, 50 V, +/- 10%, X7R, AEC-Q200 Grade 1, 0603", Cap_Case=0603, Manufacturer=TDK, PartNumber=CGA3E3X7R1H474K080AE, Supplier Part Number 1=445-172475-1-ND, TempCo=X7R, Tolerance_%=10%, Value1=Unknown, Value2=50V, ValueDisplayed=0.47uF
C40 C41 C65 C66: library part CMP-0008811-3, "CAP, CERM, 22 uF, 10 V, +/- 10%, X7R, AEC-Q200 Grade 1, 1206", Cap_Case=1206, Manufacturer=MuRata, TempCo=X7R, Tolerance_%=10%, Value1=Unknown, Value2=10V, ValueDisplayed=22uF
C45 C57 C71 C80: library part CMP-0086249-1, "CAP, CERM, 1 µF, 50 V,+/- 10%, X7R, AEC-Q200 Grade 1, 0805", Cap_Case=0805, Manufacturer=MuRata, TempCo=X7R, Tolerance_%=10%, Value2=50V, ValueDisplayed=1µF
C49: library part CMP-0006311-2, "CAP, CERM, 22 pF, 50 V, +/- 5%, C0G/NP0, AEC-Q200 Grade 1, 0402", Cap_Case=0402, Manufacturer=TDK, Supplier Part Number 1=445-12130-1-ND, TempCo=C0G/NP0, Tolerance_%=5%, Value1=Unknown, Value2=50V, ValueDisplayed=22pF
C53 C58 C64 C67 C72 C78 C81: library part CMP-0064935-4, "CAP, CERM, 0.1 uF, 100 V,+/- 10%, X7R, AEC-Q200 Grade 1, 0603", Cap_Case=0603, Manufacturer=MuRata, Supplier Part Number 1=490-13420-1-ND, TempCo=X7R, Tolerance_%=10%, Value1=Unknown, Value2=100V, ValueDisplayed=0.1uF
C54: library part CMP-0084236-1, "CAP, CERM, 0.012 µF, 50 V,+/- 10%, X7R, AEC-Q200 Grade 1, 0603", Cap_Case=0603, Manufacturer=Kemet, TempCo=X7R, Tolerance_%=10%, Value2=50V, ValueDisplayed=0.012µF
C59: library part CMP-0006354-2, "CAP, CERM, 1000 pF, 50 V, +/- 10%, X7R, AEC-Q200 Grade 1, 0402", Cap_Case=0402, Manufacturer=MuRata, Supplier Part Number 1=490-4761-1-ND, TempCo=X7R, Tolerance_%=10%, Value1=Unknown, Value2=50V, ValueDisplayed=1000pF
C63: library part CMP-0107044-1, "WCAP-ASLI Aluminum Electrolytic Capacitor, V-Chip, D8 x H6.5mm, 47uF, 50V", Capacitance Tolerance=+/-20%, Leakage Current=23.5uA, Manufacturer="Wurth Elektronik", Operating Temperature Max=105°C, Operating Temperature Min=-55°C, Rated Voltage (DC)=50V, Ripple Current=240mA
D1: library part CMP-0085759-1, "Diode, Zener, 13 V, 300 mW, AEC-Q101, SOD-323", Manufacturer="ON Semiconductor", Power_W=300mW, Value1=0.3W
D2: "LED, Red, SMD", Color=red, Manufacturer=Lite-On, PartNumber=LTST-C190CKT, Power_TotalModule=62.5mW, Value1=0.0625W, Value2=2V
D3: library part CMP-0085084-1, "Diode, TVS, Bi, 24 V, 38.9 Vc, 400 W, 10.3 A, AEC-Q101, SMA (non-polarized)", Manufacturer=Littelfuse, Value1=38.9V
D4 D6 D7 D8 D9 D10 D11 D12 D13: library part CMP-0079239-2, "Diode, Schottky, 60 V, 1 A, AEC-Q101, SOD-123", Manufacturer=Nexperia, Value1=1A, Value2=0.66V
D5: library part CMP-0002827-3, "LED, Green, SMD", Color=green, Manufacturer=Lite-On, Power_TotalModule=100mW, Value1=0.1W, Value2=2.1V
D15: library part CMP-0085742-1, "Diode, Zener, 5.6 V, 300 mW, AEC-Q101, SOD-323", Manufacturer="ON Semiconductor", Power_W=300mW, Value1=0.3W
FB1 FB2: library part CMP-0066650-1, "WE-CBA SMT EMI Suppression Ferrite Bead, size 1206, 600Ohm, 2.5A", Case/Size Code=1206, DC Resistance Max=0.048Ohm, Manufacturer="Wurth Elektronik", Operating Temperature Max=125°C, Operating Temperature Min=-55°C, Rated Current=2.5A
J1 J3 J4: library part CMP-0054578-1, "Header, 1.27 mm, 5x1, Gold, R/A, TH", Manufacturer="Sullins Connector Solutions", Supplier Part Number 1=S9016E-05-ND
J2: library part CMP-0121118-1, Current_A=1A, Digikey Part Number=S9016E-07-ND, Manufacturer=Sullins, Operating Temperature Range="-40°C to +105°C"
L1: library part CMP-0091978-1, "Shielded Power Inductor, 1uH, 20%, 17.8A IRMS, 5.8mOhm DCR max, AECQ200 Grade1, 5.28x5.48x3.1mm", Manufacturer=Coilcraft, Operating Temperature Range="to +165°C", Self Resonant Frequency=52MHz, Test Frequency=1MHz, Tolerance_%=20%
L2: library part CMP-0086950-1, "2.2µH Shielded Molded Inductor 7.5A 11.3mOhm Max 2-SMD", Manufacturer="Wurth Electronics"
L3: library part CMP-0085367-1, "Inductor, Shielded, Hyperflux, 4.7 µH, 7.4 A, 0.0143 ohm, SMD", Manufacturer="Wurth Elektronik", Value1="0.0143 ohm", Value2=7.4A, ValueDisplayed=4.7µH
L6 L7: library part CMP-0057653-2, "Inductor, Shielded, Ferrite, 47 uH, 0.35 A, 1.44 ohm, AEC-Q200 Grade 1, SMD", Manufacturer=Bourns, Supplier Part Number 1=SRN3015TA-470MCT-ND, Value1="1.44 ohm", Value2=0.35A, ValueDisplayed=47uH
LBL1: library part CMP-0003625-1, "Thermal Transfer Printable Labels, 0.650\" W x 0.200\" H - 10,000 per roll", Manufacturer=Brady, Supplier Part Number 1=97C5133
Logo1: library part CMP-0074838-1, "Texas Instrument Corporate Signature"
Logo2: library part CMP-0074844-1
Logo3: library part CMP-0074847-1, "FCC_disclaimer"
Logo4: library part CMP-0074769-1
NT1: library part CMP-0078142-6, "Single point connection between nets.", Manufacturer=N/A
NT2: library part CMP-0078142-4, "Single point connection between nets.", Manufacturer=N/A
R1 R2: library part CMP-0017777-3, "RES, 2.20, 1%, 0.25 W, AEC-Q200 Grade 0, 1206", Manufacturer=Panasonic, PartNumber=ERJ-8RQF2R2V, Power_W=250mW, Supplier Part Number 1=P2.2RCT-ND, TempCo="200 ppm/C", Tolerance_%=1%, Value2=0.25W, Value_Code=2R20, ValueDisplayed=2.20
R3: library part CMP-0026404-2, "RES, 49.9, 1%, 0.063 W, AEC-Q200 Grade 0, 0402", Manufacturer=Vishay-Dale, PartNumber=CRCW040249R9FKED, Power_W=63mW, Supplier Part Number 1=541-49.9LCT-ND, TempCo="100 ppm/C", Tolerance_%=1%, Value2=0.063W, Value_Code=49R9, ValueDisplayed=49.9
R4 R45 R48: library part CMP-0026403-2, "RES, 49.9 k, 1%, 0.063 W, AEC-Q200 Grade 0, 0402", Manufacturer=Vishay-Dale, Power_W=63mW, Supplier Part Number 1=541-49.9KLCT-ND, TempCo="100 ppm/C", Tolerance_%=1%, Value2=0.063W, Value_Code=49k9, ValueDisplayed=49.9k
R5 R16 R22 R25 R26 R35 R37 R40 R43 R56 R57: library part CMP-0026822-3, "RES, 0, 5%, 0.063 W, AEC-Q200 Grade 0, 0402", Manufacturer=Vishay-Dale, Power_W=63mW, Supplier Part Number 1=541-0.0JCT-ND, TempCo="200 ppm/C", Tolerance_%=5%, Value2=0.063W, Value_Code=0000, ValueDisplayed=0
R6: library part CMP-0026588-2, "RES, 8.06 k, 1%, 0.063 W, AEC-Q200 Grade 0, 0402", Manufacturer=Vishay-Dale, Power_W=63mW, Supplier Part Number 1=541-8.06KLCT-ND, TempCo="100 ppm/C", Tolerance_%=1%, Value2=0.063W, Value_Code=8k06, ValueDisplayed=8.06k
R7: library part CMP-0025958-3, "RES, 10.0 k, 1%, 0.063 W, AEC-Q200 Grade 0, 0402", Manufacturer=Vishay-Dale, Power_W=63mW, Supplier Part Number 1=541-10.0KLCT-ND, TempCo="100 ppm/C", Tolerance_%=1%, Value2=0.063W, Value_Code=10k0, ValueDisplayed=10.0k
R8: library part CMP-0025952-3, "RES, 102 k, 1%, 0.063 W, AEC-Q200 Grade 0, 0402", Manufacturer=Vishay-Dale, PartNumber=CRCW0402102KFKED, Power_W=63mW, Supplier Part Number 1=541-102KLCT-ND, TempCo="100 ppm/C", Tolerance_%=1%, Value2=0.063W, Value_Code=102k
R9: library part CMP-0026620-3, "RES, 9.31 k, 1%, 0.063 W, AEC-Q200 Grade 0, 0402", Manufacturer=Vishay-Dale, Power_W=63mW, Supplier Part Number 1=541-9.31KLCT-ND, TempCo="100 ppm/C", Tolerance_%=1%, Value2=0.063W, Value_Code=9k31, ValueDisplayed=9.31k
R10 R13 R24 R27 R33: library part CMP-0026196-2, "RES, 24.9 k, 1%, 0.063 W, AEC-Q200 Grade 0, 0402", Manufacturer=Vishay-Dale, Power_W=63mW, Supplier Part Number 1=541-24.9KLCT-ND, TempCo="100 ppm/C", Tolerance_%=1%, Value2=0.063W, Value_Code=24k9, ValueDisplayed=24.9k
R11 R47 R50 R53 R68: library part CMP-0026059-3, "RES, 18.2 k, 1%, 0.063 W, AEC-Q200 Grade 0, 0402", Manufacturer=Vishay-Dale, Power_W=63mW, Supplier Part Number 1=541-18.2KLCT-ND, TempCo="100 ppm/C", Tolerance_%=1%, Value2=0.063W, Value_Code=18k2, ValueDisplayed=18.2k
R12: library part CMP-0025976-3, "RES, 11.3 k, 1%, 0.063 W, AEC-Q200 Grade 0, 0402", Manufacturer=Vishay-Dale, PartNumber=CRCW040211K3FKED, Power_W=63mW, Supplier Part Number 1=541-11.3KLCT-ND, TempCo="100 ppm/C", Tolerance_%=1%, Value2=0.063W, Value_Code=11k3, ValueDisplayed=11.3k
R14: library part CMP-0021842-3, "RES, 0.47, 1%, 0.125 W, AEC-Q200 Grade 0, 0805", Manufacturer=Panasonic, Power_W=125mW, Supplier Part Number 1=P.47DCT-ND, TempCo="250 ppm/C", Tolerance_%=1%, Value2=0.125W, Value_Code=R470, ValueDisplayed=0.47
R15 R18: library part CMP-0026298-2, "RES, 33.2 k, 1%, 0.063 W, AEC-Q200 Grade 0, 0402", Manufacturer=Vishay-Dale, Power_W=63mW, Supplier Part Number 1=541-33.2KLCT-ND, TempCo="100 ppm/C", Tolerance_%=1%, Value2=0.063W, Value_Code=33k2, ValueDisplayed=33.2k
R17 R39 R52: library part CMP-0026622-3, "RES, 9.76 k, 1%, 0.063 W, AEC-Q200 Grade 0, 0402", Manufacturer=Vishay-Dale, Power_W=63mW, Supplier Part Number 1=541-9.76KLCT-ND, TempCo="100 ppm/C", Tolerance_%=1%, Value2=0.063W, Value_Code=9k76, ValueDisplayed=9.76k
R19 R21: library part CMP-0026768-2, "RES, 100 k, 0.5%, 0.063 W, AEC-Q200 Grade 0, 0402", Manufacturer=Vishay-Dale, Power_W=63mW, Supplier Part Number 1=541-100KAVCT-ND, TempCo="50 ppm/C", Tolerance_%=0.5%, Value2=0.063W, Value_Code=100k
R20: library part CMP-0026404-2, "RES, 49.9, 1%, 0.063 W, AEC-Q200 Grade 0, 0402", Manufacturer=Vishay-Dale, Power_W=63mW, Supplier Part Number 1=541-49.9LCT-ND, TempCo="100 ppm/C", Tolerance_%=1%, Value2=0.063W, Value_Code=49R9, ValueDisplayed=49.9
R23: library part CMP-0026079-3, "RES, 1.21 k, 1%, 0.063 W, AEC-Q200 Grade 0, 0402", Manufacturer=Vishay-Dale, Power_W=63mW, Supplier Part Number 1=541-1.21KLCT-ND, TempCo="100 ppm/C", Tolerance_%=1%, Value2=0.063W, Value_Code=1k21, ValueDisplayed=1.21k
R28: library part CMP-0026586-2, "RES, 88.7 k, 1%, 0.063 W, AEC-Q200 Grade 0, 0402", Manufacturer=Vishay-Dale, Power_W=63mW, Supplier Part Number 1=541-88.7KLCT-ND, TempCo="100 ppm/C", Tolerance_%=1%, Value2=0.063W, Value_Code=88k7, ValueDisplayed=88.7k
R32: library part CMP-0026411-2, "RES, 4.64 k, 1%, 0.063 W, AEC-Q200 Grade 0, 0402", Manufacturer=Vishay-Dale, Power_W=63mW, Supplier Part Number 1=541-4.64KLCT-ND, TempCo="100 ppm/C", Tolerance_%=1%, Value2=0.063W, Value_Code=4k64, ValueDisplayed=4.64k
R34: library part CMP-0026465-2, "RES, 5.36 k, 1%, 0.063 W, AEC-Q200 Grade 0, 0402", Manufacturer=Vishay-Dale, Power_W=63mW, Supplier Part Number 1=541-5.36KLCT-ND, TempCo="100 ppm/C", Tolerance_%=1%, Value2=0.063W, Value_Code=5k36, ValueDisplayed=5.36k
R36: library part CMP-0026622-3, "RES, 9.76 k, 1%, 0.063 W, AEC-Q200 Grade 0, 0402", Manufacturer=Vishay-Dale, PartNumber=CRCW04029K76FKED, Power_W=63mW, Supplier Part Number 1=541-9.76KLCT-ND, TempCo="100 ppm/C", Tolerance_%=1%, Value2=0.063W, Value_Code=9k76, ValueDisplayed=9.76k
R41 R46 R54 R59: library part CMP-0026079-3, "RES, 1.21 k, 1%, 0.063 W, AEC-Q200 Grade 0, 0402", Manufacturer=Vishay-Dale, PartNumber=CRCW04021K21FKED, Power_W=63mW, Supplier Part Number 1=541-1.21KLCT-ND, TempCo="100 ppm/C", Tolerance_%=1%, Value2=0.063W, Value_Code=1k21, ValueDisplayed=1.21k
R42 R55: library part CMP-0026208-2, "RES, 26.7 k, 1%, 0.063 W, AEC-Q200 Grade 0, 0402", Manufacturer=Vishay-Dale, Power_W=63mW, Supplier Part Number 1=541-26.7KLCT-ND, TempCo="100 ppm/C", Tolerance_%=1%, Value2=0.063W, Value_Code=26k7, ValueDisplayed=26.7k
R49: library part CMP-0026622-3, "RES, 9.76 k, 1%, 0.063 W, AEC-Q200 Grade 0, 0402", Manufacturer=Vishay-Dale, PartNumber=CRCW04029K76FKED, Power_W=63mW, Supplier Part Number 1=541-9.76KLCT-ND, TempCo="100 ppm/C", Tolerance_%=1%, Value2=0.063W, Value_Code=9k76, ValueDisplayed=9.76K
T1 T2: library part CMP-0092994-1, "TRANSFORMER", Frequency_Fixed=1MHz, Manufacturer=Wurth, Operating Temperature Range=to
U1: library part CMP-0032941-1, "Automotive, 36-V, 4-Switch, Integrated Buck-boost Converter", Manufacturer="Texas Instruments", Max Supply Voltage=36V, Min Supply Voltage=3V, Nominal Supply Current=760uA, Operating Temperature Range="-40°C to +125°C", Output Voltage=0.8-22V, Switching Frequency=200-2200kHz
U2: library part CMP-0092866-1, "3-V to 36-V, Low EMI Synchronous Step-Down Converter", Manufacturer="Texas Instruments", Max Supply Voltage=36V, Min Supply Voltage=3V, Nominal Supply Current=9uA, Operating Temperature Range="-40°C to +150°C", Output Voltage=1-34.2V, Switching Frequency=200-2200kHz
U3: library part CMP-0086101-2, "60V, 2A Integrated Ideal Diode with Over-Voltage & OverCurrent protection, PWP0016H (HTSSOP-16)", Alternate Manufacturer="Texas Instruments"
U4 U6: library part CMP-0092987-2, "Low-Noise 36V Push-Pull Transformer Driver with Duty Cycle Control for Isolated Power Supplies", Manufacturer="Texas Instruments", Operating Temperature Range="-55°C to +150°C"
U5 U7: library part CMP-0033164-1, "Automotive Catalog Adjustable Precision Shunt Regulator, 34 ppm / degC, 100 mA, -40 to 125 degC, 3-pin SOT-23 (DBZ), Green (RoHS & no Sb/Br)", Manufacturer="Texas Instruments", PartNumber=TL431AQDBZRQ1, Rating=Automotive, Temp Coeff(Typ)(ppm/ degree C)=34
ZZ1: library part CMP-0003616-3
ZZ2: library part CMP-0077236-1
ZZ3: library part CMP-0077237-1
ZZ4: library part CMP-0077238-1

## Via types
v1: diameter 0.406, hole 0.203, Top Layer to Bottom Layer, 57 vias
v2: diameter 0.6, hole 0.3, Top Layer to Bottom Layer, 46 vias
v3: diameter 0.5, hole 0.203, Top Layer to Bottom Layer, 6 vias
v4: diameter 0.5, hole 0.203, Top Layer to Bottom Layer, tented both sides, 6 vias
